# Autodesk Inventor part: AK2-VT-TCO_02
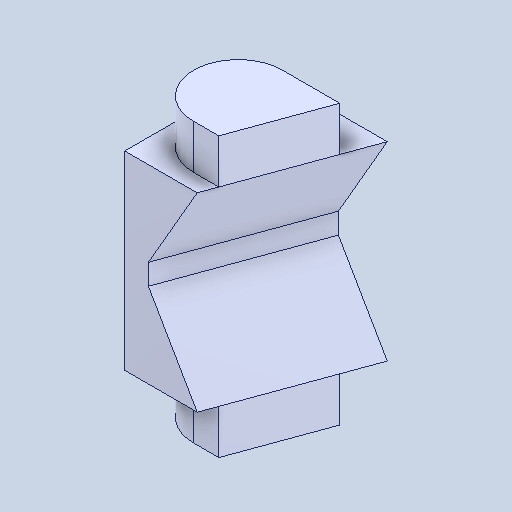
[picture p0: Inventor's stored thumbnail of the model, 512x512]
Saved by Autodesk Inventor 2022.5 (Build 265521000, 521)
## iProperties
Created: 2024-07
Part Number: AK2-VT-TCO_02
Material: 一般
Document SubType Name: Modeling
Designer: ImaoCorp
Density: 1 g/cm^3
Appearance: 既定
Author: ImaoCorp
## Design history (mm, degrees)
feature "AK2-VT-TCO_02"
node "ソリッド1"
